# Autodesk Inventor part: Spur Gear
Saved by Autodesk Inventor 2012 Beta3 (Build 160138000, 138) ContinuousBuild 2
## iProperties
Created: 2011-01
Part Number: Spur Gear
Material: Steel
Document SubType Name: Modeling
Designer: Beta-8540w
Categories: <?xml version="1.0" encoding="UTF-16"?> <MemberInstance><Categories><FamilyTemplate><FamilyTemplateParameter ValueType="xs:double" Id="1" ObjectReferenceKey="da
Density: 1 g/cm^3
CustomPartVersion: 1
Author: Beta-8540w
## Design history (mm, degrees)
sketch "Sketch1"
  geometry: C1 r 40.8 at (0, 0)
  constraints: 1 centre point
  dimensions: "d0" = 81.6 diameter of C1 (= da_da)
extrude "Extrusion1" new body sketch "Sketch1" distance "d1" = 13 (= da_b); taper "d2" = 0 deg
workplane "Work Plane2"
sketch "Sketch2"
  geometry: C1 r 40.8 at (0, 0) reference; C2 r 40 at (0, 0)
  constraints: 1 centre point, 1 coincident
  dimensions: "d3" = 80 diameter of C2 (= da_dw)
feature "Pitch Diameter" sketch "Sketch2" dims "d4" = 10, "d5" = 0
workplane "Work Plane8"
workplane "Work Plane9"
feature "Spur Gear" dims "da_b" = 13, "da_d" = 80, "da_aw" = 50, "da_da" = 81.6, "da_df" = 78, "da_dw" = 80, angle "da_beta" = 0 deg, "da_lefttooth" = 0, "da_righttooth" = 0
node "Keyway1"
body "Solid1"
body "Srf1"
feature "Hub Keyway"
other parameters: "d17" = 0, "d34" = 0.31416 (computed from da_z), "d39" = 0, "d41" = 0, "d47" = 0, "d48" = 0
